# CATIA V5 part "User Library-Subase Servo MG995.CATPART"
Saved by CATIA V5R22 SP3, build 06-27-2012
Part number: E631A6AC-CDCF-4520-83F0-9E73EDFC1F5E
Revision: ANY
Definition: UNKNOWN
Nomenclature: E631A6AC-CDCF-4520-83F0-9E73EDFC1F5E
Source: Unknown
Bounding box of the stored display mesh (mm): x -26 to 26, y -18.75 to 28.25, z -10 to 10
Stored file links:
  \\PSSILO\catalogs\ContentCentral\Subase Servo MG995\Cache\E631A6AC-CDCF-4520-83F0-9E73EDFC1F5E.CATPart
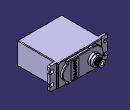
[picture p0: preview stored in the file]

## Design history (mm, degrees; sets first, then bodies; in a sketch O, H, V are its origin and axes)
Body1 "Extrude11" (main body)
  Solid1: solid without history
